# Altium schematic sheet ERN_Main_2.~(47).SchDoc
size A; SheetNumber: 2; SheetTotal: 4; SPICEModelCacheYVUKJMZF: <root> / <DocumentId>YVUKJMZF</DocumentId> / <CacheFrame Number="0"> / <Model Name="1n5400" Kind="MDL"> / <Text>*1N5400 MCE / * 50V 3A Si Rectifier pkg:DO-201 1,2 / .MODEL 1N5400 D(IS=2.68E-12 RS=0.00977 N=1.17 TT=1.44E-5 CJO=1.24E-10 / + VJ=0.6 M=0.333 BV=66.6 IBV=1E-5 )</Text> / </Model> / <Model Name="led2" Kind="MDL"> / <Text>*Typ RED,GREEN,YELLOW,AMBER GaAs LED: Vf=2.1V Vr=4V If=40mA trr=3uS / *LED Pinout: 1=A, 2=K / .MODEL LED2 D (IS=93.1P RS=42M N=4.61 BV=4 IBV=10U / + CJO=2.97P VJ=.75 M=.333 TT=4.32U)</Text> / </Model> / </CacheFrame> / </root>
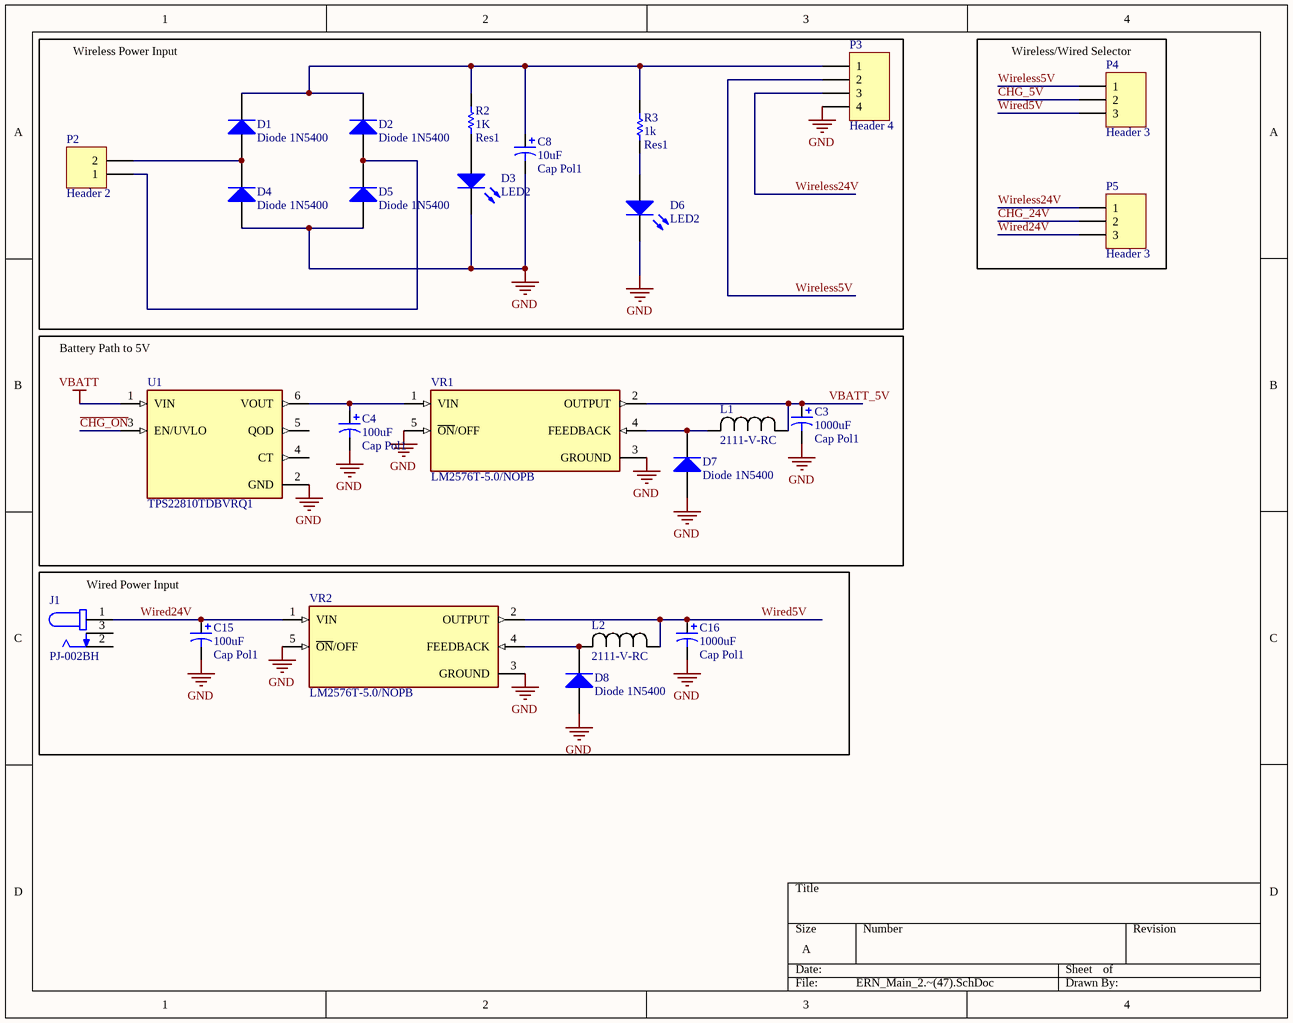
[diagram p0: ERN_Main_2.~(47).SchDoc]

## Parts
C3  Cap Pol1  value 1000uF  [RB7.6-15]
C4  Cap Pol1  value 100uF  [RB7.6-15]
C8  Cap Pol1  value 10uF  [RB7.6-15]
C15  Cap Pol1  value 100uF  [RB7.6-15]
C16  Cap Pol1  value 1000uF  [RB7.6-15]
D1  Diode 1N5400  [DO-201AD]
D2  Diode 1N5400  [DO-201AD]
D3  LED2  [3.2X1.6X1.1]
D4  Diode 1N5400  [DO-201AD]
D5  Diode 1N5400  [DO-201AD]
D6  LED2  [3.2X1.6X1.1]
D7  Diode 1N5400  [DO-201AD]
D8  Diode 1N5400  [DO-201AD]
J1  PJ-002BH  [CUI_PJ-002BH]
L1  2111-V-RC  [IND_21XX_27A_V]
L2  2111-V-RC  [IND_21XX_27A_V]
P2  Header 2  [HDR1X2]
P3  Header 4  [HDR1X4]
P4  Header 3  [HDR1X3]
P5  Header 3  [HDR1X3]
R2  Res1  value 1K  [AXIAL-0.3]
R3  Res1  value 1k  [AXIAL-0.3]
U1  TPS22810TDBVRQ1  [SOT95P280X145-6N]
VR1  LM2576T-5.0/NOPB  [TO170P1067X483X1651-5]
VR2  LM2576T-5.0/NOPB  [TO170P1067X483X1651-5]

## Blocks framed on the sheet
Wireless Power Input: C8 D1-D6 P2 P3 R2 R3
Wireless/Wired Selector: P4 P5
Battery Path to 5V: C3 C4 D7 L1 U1 VR1
Wired Power Input: C15 C16 D8 J1 L2 VR2

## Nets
GND: C3.2 C4.2 C8.2 C15.2 C16.2 D3.2(K) D4.1(A) D5.1(A) D6.2(K) D7.1(A) D8.1(A) P3.4 U1.2(GND) VR1.3(GROUND) VR1.5(~{ON}/OFF) VR2.3(GROUND) VR2.5(~{ON}/OFF)
VBATT: U1.1(VIN)
~{CHG_ON}: U1.3(EN/UVLO)
CHG_5V: P4.2
CHG_24V: P5.2
VBATT_5V: C3.1 L1.1 VR1.2(OUTPUT)
Wired5V: C16.1 L2.1 P4.3 VR2.2(OUTPUT)
Wired24V: C15.1 J1.1 P5.3 VR2.1(VIN)
Wireless5V: P3.2 P4.1
Wireless24V: P3.3 P5.1
NetC4_1: C4.1 U1.6(VOUT) VR1.1(VIN)
NetC8_1: C8.1 D1.2(K) D2.2(K) P3.1 R2.2 R3.2
NetD1_1: D1.1(A) D4.2(K) P2.2
NetD2_1: D2.1(A) D5.2(K) P2.1
NetD3_1: D3.1(A) R2.1
NetD6_1: D6.1(A) R3.1
NetD7_2: D7.2(K) L1.2 VR1.4(FEEDBACK)
NetD8_2: D8.2(K) L2.2 VR2.4(FEEDBACK)

Not connected (* = marked no-connect by the designer): J1 2 3; U1 4(CT) 5(QOD)

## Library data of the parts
C3 C4 C8 C15 C16 = Cap Pol1: Polarized Capacitor (Radial)
D1 D2 D4 D5 D7 D8 = Diode 1N5400: 3 Amp General Purpose Rectifier
D3 D6 = LED2: Typical RED, GREEN, YELLOW, AMBER GaAs LED
J1 = PJ-002BH: 2.5 x 6.5 mm, 5.0 A, Horizontal, Through Hole, Dc Power Jack Connector; MF: Same Sky
L1 L2 = 2111-V-RC: Inductor 68uH; Manufacturer_Name: Bourns Electronics
P2 = Header 2: Header, 2-Pin
P3 = Header 4: Header, 4-Pin
P4 P5 = Header 3: Header, 3-Pin
R2 R3 = Res1: Resistor
U1 = TPS22810TDBVRQ1: Automotive 1-channel, 18-V, 2-A, 79-mâ„¦ load switch with adj. rise time and adj. output discharge; MF: Texas Instruments
VR1 VR2 = LM2576T-5.0/NOPB: SIMPLE SWITCHERÂ® 40V, 3A Low Component Count Step-Down Regulator; MF: Texas Instruments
